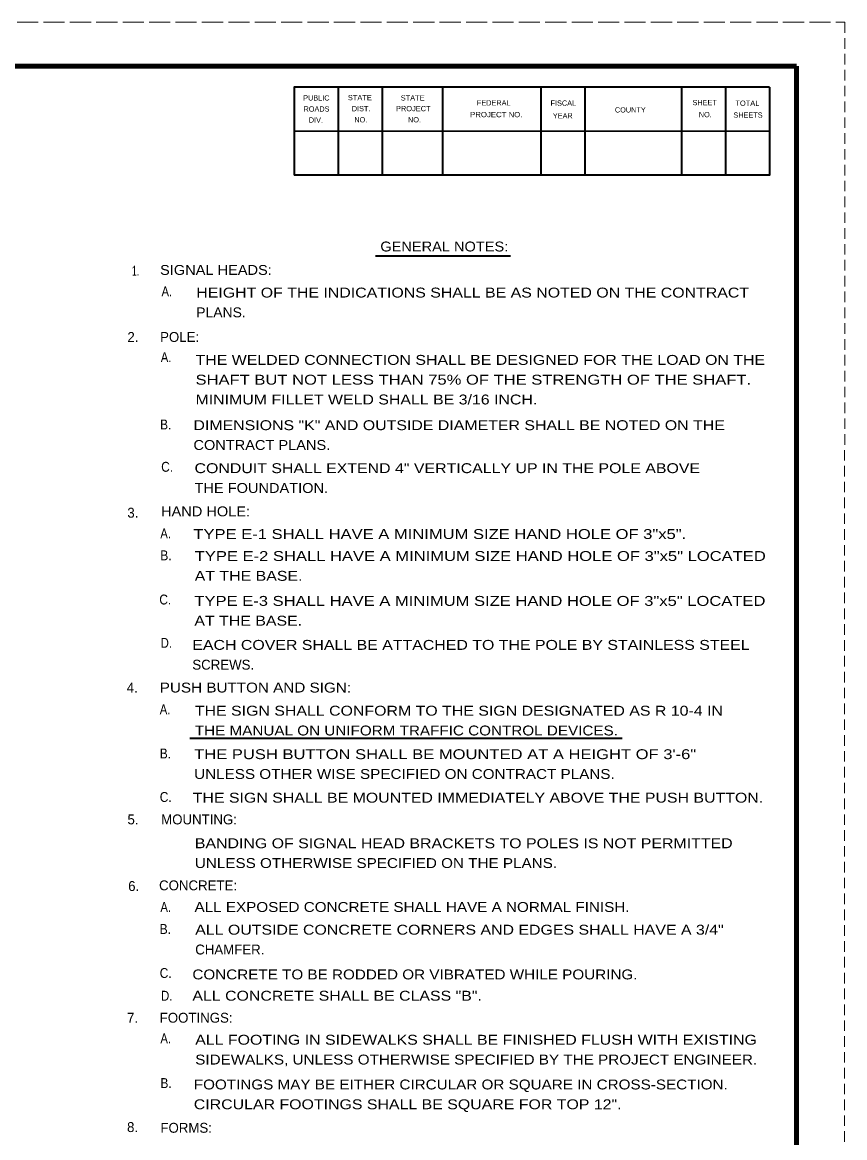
# Model space of a CAD drawing. Extents: x -608 to 72, y 36 to 476.
# Drawn here: x -114.6 to 72.2, y 222.1 to 475.6 of the extents above; entities that cross this region are included whole.
import ezdxf
from ezdxf.enums import TextEntityAlignment as Align

# ---------------------------------------------------------------- set-up
doc = ezdxf.new("R2010")
doc.units = 0
doc.header["$LTSCALE"] = 0.8
doc.linetypes.add('LONG_DASHED', pattern=[7.5, 6, -1.5])
doc.linetypes.add('MEDIUM_DASHED', pattern=[4.5, 3, -1.5])
doc.layers.add('1', color=7, linetype='Continuous', lineweight=53)
doc.layers.add('61', color=7, linetype='Continuous', lineweight=35)

msp = doc.modelspace()

# ---------------------------------------------------------------- linework, layer by layer
at = {"layer": '1', "linetype": 'MEDIUM_DASHED', "lineweight": 13}
msp.add_line((72.1969, 475.5947), (72.1769, 35.5747), dxfattribs=at)
at = {"layer": '1', "lineweight": 35}
for p, q in [((-34.3747, 422.5165), (-3.6867, 422.5165)), ((-76.5489, 312.9505), (21.6367, 312.9505))]:
    msp.add_line(p, q, dxfattribs=at)
at = {"layer": '61', "linetype": 'LONG_DASHED', "lineweight": 13}
msp.add_line((-607.8231, 475.5947), (72.1969, 475.5947), dxfattribs=at)
at = {"layer": '61', "lineweight": 158}
msp.add_line((61.2169, 465.5947), (61.2369, 45.5547), dxfattribs=at)
at = {"layer": '61'}
for p, q in [((-42.8631, 460.8347), (-42.8631, 440.8347)), ((-32.8631, 460.8347), (-32.8631, 440.8347)), ((-19.1831, 460.8347), (-19.1831, 440.8347)), ((3.1369, 460.8347), (3.1369, 440.8347)), ((13.1369, 460.8347), (13.1369, 440.8347)), ((35.1169, 460.8547), (35.1169, 440.8547)), ((45.1169, 460.8547), (45.1169, 440.8547)), ((55.1369, 450.8147), (-52.8831, 450.8347))]:
    msp.add_line(p, q, dxfattribs=at)
at = {"layer": '61', "lineweight": 158}
msp.add_lwpolyline([(61.2169, 465.5947), (-577.8231, 465.5947), (-577.8231, 45.5747)], dxfattribs=at)
at = {"layer": '61'}
for points in [[(55.1169, 460.8547), (-52.8631, 460.8347), (-52.8631, 440.8347)], [(55.1169, 460.8547), (55.1169, 440.8547), (-52.8631, 440.8347)]]:
    msp.add_lwpolyline(points, dxfattribs=at)

# ---------------------------------------------------------------- texts
at = {"layer": '1', "width": 1.1}
msp.add_text('GENERAL NOTES:', height=2.25, dxfattribs=at).set_placement((-18.7647, 423.5202), align=Align.CENTER)
at = {"layer": '1'}
for s, width, p in [('1.', 0.65, (-89.7197, 418.0212)), ('SIGNAL HEADS:', 1.1, (-83.3337, 418.1985)), ('A.', 0.85, (-83.0023, 413.3159)), ('HEIGHT OF THE INDICATIONS SHALL BE AS NOTED ON THE CONTRACT', 1.2, (-75.1087, 413.0537)), ('PLANS.', 1.05, (-75.1087, 408.5537)), ('A.', 0.85, (-83.1696, 398.3847)), ('THE WELDED CONNECTION SHALL BE DESIGNED FOR THE LOAD ON THE', 1.2, (-75.2771, 397.7533)), ('SHAFT BUT NOT LESS THAN 75% OF THE STRENGTH OF THE SHAFT.', 1.25, (-75.2771, 393.2533)), ('MINIMUM FILLET WELD SHALL BE 3/16 INCH.', 1.2, (-75.2771, 388.7533)), ('B.', 0.9, (-83.3275, 383.0737)), ('DIMENSIONS "K" AND OUTSIDE DIAMETER SHALL BE NOTED ON THE', 1.2, (-75.7506, 382.9158)), ('CONTRACT PLANS.', 1.1, (-75.7506, 378.4158)), ('C.', 0.9, (-83.079, 373.4552)), ('CONDUIT SHALL EXTEND 4" VERTICALLY UP IN THE POLE ABOVE', 1.2, (-75.5018, 373.146)), ('THE FOUNDATION.', 1.1, (-75.5018, 368.646)), ('HAND HOLE:', 1.1, (-83.1139, 363.3326)), ('A.', 0.85, (-83.2702, 358.3338)), ('TYPE E-1 SHALL HAVE A MINIMUM SIZE HAND HOLE OF 3"x5".', 1.25, (-75.772, 358.1776)), ('B.', 0.9, (-83.2701, 353.3351)), ('TYPE E-2 SHALL HAVE A MINIMUM SIZE HAND HOLE OF 3"x5" LOCATED', 1.25, (-75.4596, 353.1789)), ('AT THE BASE.', 1.2, (-75.4596, 348.6789)), ('C.', 0.9, (-83.5043, 343.2991)), ('TYPE E-3 SHALL HAVE A MINIMUM SIZE HAND HOLE OF 3"x5" LOCATED', 1.25, (-75.5376, 342.9867)), ('AT THE BASE.', 1.2, (-75.5376, 338.4867)), ('D.', 0.85, (-83.1919, 333.4577)), ('EACH COVER SHALL BE ATTACHED TO THE POLE BY STAINLESS STEEL', 1.2, (-76.0062, 332.9892)), ('PUSH BUTTON AND SIGN:', 1.15, (-83.4028, 323.2925)), ('A.', 0.85, (-83.4027, 318.3513)), ('THE SIGN SHALL CONFORM TO THE SIGN DESIGNATED AS R 10-4 IN', 1.2, (-75.4333, 318.0326)), ('THE MANUAL ON UNIFORM TRAFFIC CONTROL DEVICES.', 1.15, (-75.4333, 313.5326)), ('B.', 0.9, (-83.4028, 308.3097)), ('THE PUSH BUTTON SHALL BE MOUNTED AT A HEIGHT OF 3\'-6"', 1.25, (-75.5927, 308.1502)), ('UNLESS OTHER WISE SPECIFIED ON CONTRACT PLANS.', 1.15, (-75.5927, 303.6502)), ('C.', 0.9, (-83.4028, 298.4273)), ('THE SIGN SHALL BE MOUNTED IMMEDIATELY ABOVE THE PUSH BUTTON.', 1.2, (-75.9114, 298.2679)), ('BANDING OF SIGNAL HEAD BRACKETS TO POLES IS NOT PERMITTED', 1.2, (-75.4333, 287.9074)), ('UNLESS OTHERWISE SPECIFIED ON THE PLANS.', 1.15, (-75.4333, 283.4074)), ('A.', 0.85, (-83.2528, 273.428)), ('ALL EXPOSED CONCRETE SHALL HAVE A NORMAL FINISH.', 1.15, (-75.5084, 273.4279)), ('B.', 0.9, (-83.4142, 268.4264)), ('ALL OUTSIDE CONCRETE CORNERS AND EDGES SHALL HAVE A 3/4"', 1.2, (-75.3472, 268.2652)), ('C.', 0.9, (-83.4142, 258.4233)), ('CONCRETE TO BE RODDED OR VIBRATED WHILE POURING.', 1.15, (-75.9925, 258.1007)), ('D.', 0.85, (-83.0915, 253.2605)), ('ALL CONCRETE SHALL BE CLASS "B".', 1.2, (-75.9925, 253.2605)), ('A.', 0.85, (-83.2528, 243.5801)), ('ALL FOOTING IN SIDEWALKS SHALL BE FINISHED FLUSH WITH EXISTING', 1.2, (-75.3472, 243.2574)), ('SIDEWALKS, UNLESS OTHERWISE SPECIFIED BY THE PROJECT ENGINEER.', 1.15, (-75.3472, 238.7574)), ('B.', 0.9, (-83.2528, 233.4157)), ('FOOTINGS MAY BE EITHER CIRCULAR OR SQUARE IN CROSS-SECTION.', 1.15, (-75.6698, 233.093)), ('CIRCULAR FOOTINGS SHALL BE SQUARE FOR TOP 12".', 1.2, (-75.6698, 228.593))]:
    msp.add_text(s, height=2.25, dxfattribs=dict(at, width=width)).set_placement(p)
for s, p in [('2.', (-90.7464, 402.9624)), ('POLE:', (-83.3274, 402.9624)), ('3.', (-90.7682, 363.0202)), ('SCREWS.', (-76.0062, 328.4892)), ('4.', (-90.8942, 323.2925)), ('5.', (-90.7348, 293.3268)), ('MOUNTING:', (-83.084, 293.3268)), ('6.', (-90.5754, 278.1846)), ('CONCRETE:', (-83.5622, 278.3439)), ('CHAMFER.', (-75.3472, 263.7652)), ('7.', (-90.8358, 248.2589)), ('FOOTINGS:', (-83.4142, 248.2589)), ('8.', (-90.8358, 223.4126)), ('FORMS:', (-83.2528, 223.2512))]:
    msp.add_text(s, height=2.25, dxfattribs=at).set_placement(p)
at = {"layer": '61'}
for s, rotation, p in [('PUBLIC', 0.033, (-50.8231, 457.8147)), ('ROADS', 0.124, (-50.7431, 455.2947)), ('DIST.', 0.056, (-39.7831, 455.3747)), ('FEDERAL', 0.007, (-11.3631, 456.6947)), ('FISCAL', 359.942, (5.3769, 456.6347)), ('COUNTY', 0.069, (19.9969, 455.0947)), ('SHEET', 0.059, (37.6369, 456.7547)), ('DIV.', 359.932, (-49.5431, 452.7947)), ('YEAR', 0.105, (5.8969, 453.7347)), ('SHEETS', 359.959, (46.9169, 453.9147))]:
    msp.add_text(s, height=1.201, rotation=rotation, dxfattribs=at).set_placement(p)
for s, rotation, width, p in [('STATE', 0.059, 1.05, (-40.6631, 457.8747)), ('STATE', 0.059, 1.05, (-28.6631, 457.8147)), ('PROJECT', 359.908, 1.05, (-29.7431, 455.3947)), ('TOTAL', 359.926, 1.05, (47.3769, 456.6147)), ('NO.', 359.852, 0.95, (-39.2031, 452.8547)), ('NO.', 0.225, 0.95, (-27.0031, 452.8547)), ('PROJECT NO.', 359.922, 1.1, (-12.9031, 454.0347)), ('NO.', 359.852, 0.95, (39.0569, 454.0347))]:
    msp.add_text(s, height=1.201, rotation=rotation, dxfattribs=dict(at, width=width)).set_placement(p)

doc.saveas('drawing.dxf')
